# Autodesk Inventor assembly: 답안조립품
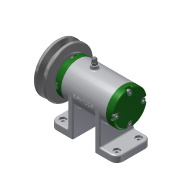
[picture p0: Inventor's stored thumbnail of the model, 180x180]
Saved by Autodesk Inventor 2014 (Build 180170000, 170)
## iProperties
Created: 2017-02
Part Number: 답안조립품
Document SubType Name: Assembly
Designer: SCD-A14
Author: SCD-A14
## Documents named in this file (16)
- C:\Users\SCD-A14\Desktop\470208V1001\답안조립품.iam
- C:\Users\SCD-A14\Desktop\470208V1001\본체.ipt
- C:\Users\SCD-A14\Desktop\470208V1001\V벨트풀리.ipt
- C:\Users\SCD-A14\Desktop\470208V1001\너트 M 8.ipt
- C:\Users\SCD-A14\Desktop\470208V1001\니플 M 6 x 0.75.ipt
- C:\Users\SCD-A14\Desktop\470208V1001\뒤커버.ipt
- C:\Users\SCD-A14\Desktop\470208V1001\베어링 15 x 32 x 9.ipt
- C:\Users\SCD-A14\Desktop\470208V1001\볼트 M 6 x 8.ipt
- C:\Users\SCD-A14\Desktop\470208V1001\볼트 M4 x 12.ipt
- C:\Users\SCD-A14\Desktop\470208V1001\스프링와셔 8.ipt
- C:\Users\SCD-A14\Desktop\470208V1001\앞커버.ipt
- C:\Users\SCD-A14\Desktop\470208V1001\오일 실 15 25 7.ipt
- C:\Users\SCD-A14\Desktop\470208V1001\와셔 6x11.5.ipt
- C:\Users\SCD-A14\Desktop\470208V1001\와셔 8x17.ipt
- C:\Users\SCD-A14\Desktop\470208V1001\축.ipt
- C:\Users\SCD-A14\Desktop\470208V1001\키 3 x 3 x 12.ipt
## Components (11 placed, 3 different names)
1. V벨트풀리:1 — 각도:2
2. KS B 2023 6002 - 15 x 32 x 9:1
3. KS B 2023 6002 - 15 x 32 x 9:2
4. ISO 4762 M4 x 12:1
5. ISO 4762 M4 x 12:2
6. ISO 4762 M4 x 12:3
7. ISO 4762 M4 x 12:4
8. ISO 4762 M4 x 12:5
9. ISO 4762 M4 x 12:6
10. ISO 4762 M4 x 12:7
11. ISO 4762 M4 x 12:8
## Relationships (1: Angle 1)
- 각도:2 [Angle]: V벨트풀리:1
